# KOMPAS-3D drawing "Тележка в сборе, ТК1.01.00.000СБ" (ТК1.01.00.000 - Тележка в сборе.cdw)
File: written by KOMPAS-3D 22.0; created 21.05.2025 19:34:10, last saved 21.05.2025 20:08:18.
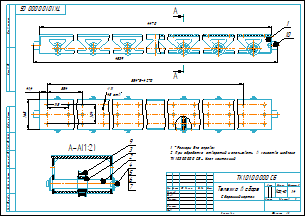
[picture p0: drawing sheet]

Sheet 1: A3, landscape

Document properties: Автор: user; Масса: 103.447138; Полное имя файла: Тележка в сборе.a3d

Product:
- Part/product: Тележка в сборе  | designation ТК1.01.00.000СБ
    Масса: 103.447138
    Форматы листов документа: A3
    source file: ТК1.01.00.000 - Тележка в сборе.spw
  - Component [detail]: Ролик LFR5206-25-NPP  | qty 6  | pos. 9  | Масса: 0.442345; Раздел спецификации: Прочие изделия; source file: Ролик LFR5206-25-NPP.m3d
  - Component [detail]: Ролик LFR5206-25-NPP  | qty 2  | Раздел спецификации: Прочие изделия; source file: Ролик LFR5206-25-NPP.m3d
  - Component [assembly]: Корпус тележки  | designation ТК1.01.01.000СБ  | qty 1  | pos. 1  | Масса: 95.296281; Форматы листов документа: A4@4~3; source file: Корпус тележки\КД\ТК1.01.01.000 - Корпус тележки.spw, Корпус тележки\КД\ТК1.01.01.000 СБ - Корпус тележки.cdw, Корпус тележки\Корпус тележки.a3d
  - Component [detail]: Ось  | designation ТК1.01.00.001  | qty 6  | pos. 2  | Материал: Сталь 40Х ГОСТ 4543-2016 (density 7850 kg/m3); Масса: 0.62382; Форматы листов документа: A4; source file: Ось.m3d, ТК1.01.00.001 - Ось.cdw
  - Component [standard]: Шайба C 24 ГОСТ 10450-78  | qty 12  | pos. 6  | Масса: 0.020839; Раздел спецификации: Стандартные изделия; Рассекать на разрезах: no
  - Component [standard]: Шайба A 12 ГОСТ 6958-78  | qty 12  | pos. 5  | Масса: 0.022195; Раздел спецификации: Стандартные изделия; Рассекать на разрезах: no
  - Component [standard]: Шайба 12 ГОСТ 6402-70  | qty 12  | pos. 4  | Масса: 0.00345; Раздел спецификации: Стандартные изделия; Рассекать на разрезах: no; additional columns: 12
  - Component [standard]: Винт с полукруглой головкой  | qty 12  | pos. 7  | Масса: 0.037647; Раздел спецификации: Стандартные изделия; Рассекать на разрезах: no; additional columns: Винт с полукруглой головкой и шестигранным углублением; ГОСТ ISO 7380-1; М12 x 30 - 08.8
  - Component [standard]: Кольцо A25.50 ХГА.Ц9.хр ГОСТ 13942-86  | qty 12  | pos. 3  | Материал: Сталь 50 ХГА ГОСТ 14959-2016 (density 7850 kg/m3); Масса: 0.002684; Раздел спецификации: Стандартные изделия; Рассекать на разрезах: no
  - Component [detail]: Ролик LFR5206-25-NPP  | qty 5  | pos. 9  | Раздел спецификации: Прочие изделия; source file: Ролик LFR5206-25-NPP.m3d
  - Component [assembly]: Узел монтажный  | designation ТК1.03.00.000СБ  | qty 1  | pos. 10  | Форматы листов документа: A3; source file: ..\Узел монтажный\Узел монтажный _ ТК1.03.00.000 СБ.cdw, ..\Узел монтажный\Узел монтажный.a3d
  - Component [detail]: Демпфер покупной  | qty 1  | pos. 3  | Масса: 0.356039; source file: ..\Упор отбойник.m3d
  - Component [detail]: Демпфер покупной  | qty 1  | pos. 4  | Масса: 0.356039; source file: ..\Упор отбойник.m3d

Title block, sheet 1: Наименование: Тележка в сборе / Сборочный чертеж; Масса: 103,45; Количество листов документа: 1; Форматы листов документа: A3; stored path: D:\Работа\2025\5. Май\Задание №6 - Тележка для крыши\3Д\Тележка в сборе\ТК1.01.00.000 - Тележка в сборе.cdw

Views: Вид 1, Местный разрез 1, Слева, Разрез А-А
Referenced files in D:\Работа\2025\5. Май\Задание №6 - Тележка для крыши\3Д\Тележка в сборе\Корпус тележки\: Ребро продольное.m3d, Верхняя пластина.m3d, Пластина нижняя.m3d, Стенка боковая.m3d, Корпус тележки.a3d
Referenced files in D:\Работа\2025\5. Май\Задание №6 - Тележка для крыши\3Д\Тележка в сборе\: Ось.m3d, Тележка в сборе.a3d, Ролик LFR5206-25-NPP.m3d, ТК1.01.00.001 - Ось.cdw
Referenced files in D:\Работа\2025\5. Май\Задание №6 - Тележка для крыши\3Д\Тележка в сборе\Корпус тележки\КД\: ТК1.01.01.000 - Корпус тележки.spw, ТК1.01.01.000 СБ - Корпус тележки.cdw
Referenced files in D:\Работа\2025\5. Май\Задание №6 - Тележка для крыши\3Д\: Упор отбойник.m3d
Referenced files in D:\Program Files\ASCON\KOMPAS-3D v22\Libs\PolynomLib\DATA\vault\Methods\Kompas\3D\: PLib_Nut_OST92_900.m3d, PLib_Washer_1_712.m3d, PLib_Washer_2_712.m3d, PLib_Screw_ISO_7380_1500.m3d, PLib_Check_spring_rings_GOST_13942_911.m3d
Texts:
  ТК1.01.00.000
  Слой 1
  Ролик LFR5206-25-NPP
  ТК1.01.01.000
  ТК1.01.01.000
  Корпус тележки
  ТК1.01.01.000 СБ
  ТК1.01.01.000       СБ
  Шайба C 24 ГОСТ 10450-78
  Крепежное изделие ГОСТ
  Шайба
  ГОСТ
  BOSimple***PART:51412fb7-6d63-7ba7-1d1b-63d03bb2bc0a***SHORTLOC:Root±140±10±10±60±20±20[Нет;Без покрытия;Без указания материала;-;24]
  Шайба A 12 ГОСТ 6958-78
  BOSimple***PART:bdb4ee81-67e8-b5c4-1761-ea9b438f428c***SHORTLOC:Root±140±10±10±60±10±20[Нет;Без покрытия;Без указания материала;-;12]
  Шайба 12 ГОСТ 6402-70
  BOSimple***PART:7e278679-a80e-6205-d4ad-2f05a66bfd42***SHORTLOC:Root±140±10±30±110[Нет;Без покрытия;Без указания материала;12]
  Винт с полукруглой головкой
  Винт с полукруглой головкой и шестигранным углублением
  ГОСТ ISO
  BOSimple***PART:22d0d234-c3fb-7cb5-7557-87eacf75c581***SHORTLOC:BD5A_871C2A98F8294977[1,75;30;12;Без покрытия;-;Не требуется покрытия;Без обработки;8.8;Steel]
  Кольцо A25.50 ХГА.Ц9.хр ГОСТ 13942-86
  Кольцо
  Ц9.хр
  BOSimple***PART:358777da-06df-04f2-faa3-d060e7cf20e1***SHORTLOC:B2AE_C71AD39EB7EB4E6E[25;A;9;Цинковое, хроматированное;2;Сталь 50 ХГА ГОСТ 14959-2016]
  Демпфер
  ТК1.01.00.001
  Ось
  BOSimple***Material:5b3b2396-5625-11d7-8827-00508b01a93a
  Стенка боковая
  ТК1.01.01.001
  ТК1.01.01.001-01 Стенка боковая
  ТК1.01.01.001 Стенка боковая
  Ребро продольное
  ТК1.01.01.004
  ТК1.01.01.004 Ребро продольное
  ТК1.01.01.004-01 Ребро продольное
  Верхняя пластина
  ТК1.01.01.003
  ТК1.01.01.003 Верхняя пластина
  Пластина нижняя
  ТК1.01.01.002
  ТК1.01.01.002 Пластина нижняя
  Гайка М12-6H(S18) ГОСТ 5915-70
  ТК1.01.01.000 Корпус тележки
  ТК1.01.00.001 Ось
  Узел монтажный
  ТК1.03.00.000
  ТК1.03.00.000 Узел монтажный
  Демпфер покупной
  ТК1.01.00.000
  ТК1.01.00.000 СБ Тележка в сборе
Dimensions and other numbers on the sheet: 4470; 1; 4539; 10; 0; 2; 7; 4; 5; 6; 9; 3; 58; 40Х; 019; 12; -1 -; 08.8; 50 ХГА; -01; 11; 1:4; 103,45; 01

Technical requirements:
  *Размеры для справок.
  При обработке отверстий использовать в качестве шаблона
  ТК1.03.00.000 СБ - Узел монтажный.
